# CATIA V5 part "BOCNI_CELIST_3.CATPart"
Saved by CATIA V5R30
Part number: BOCNI_CELIST_3
Bounding box of the stored display mesh (mm): x -40 to 40, y 37.031 to 109.038, z -36.619 to -1.271
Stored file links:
  C:\Users\ondra\Desktop\PŘÍLOHA P III\CATIA\BOCNI_CELIST_3.CATPart
  C:\Users\ondra\Desktop\FORMA_BAKALARKA\Part1.CATPart
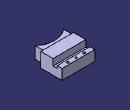
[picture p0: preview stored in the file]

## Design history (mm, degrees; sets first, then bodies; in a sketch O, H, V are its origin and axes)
Body1 (main body)
  Body2 "BOCNI TVARNIK 3"
    Solid1: linked copy from another document
  Assemble1: tool Body2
